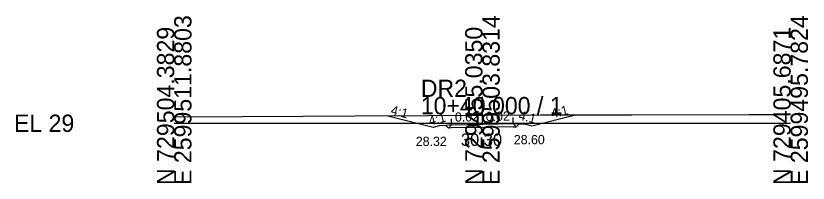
# Model space of a CAD drawing. Extents: x -26 to 1162, y -10 to 9515.
# Drawn here: x -25.7 to 102.8, y 1990.3 to 2017.4 of the extents above; entities that cross this region are included whole.
import ezdxf

# ---------------------------------------------------------------- set-up
doc = ezdxf.new("R2010")
doc.units = 0
for name, color, linetype in [('Exist Cross Section Cell', 7, 'Continuous'), ('Exist XS Center Line Elevation Label', 7, 'Continuous'), ('Exist XS Ground Line', 7, 'Continuous'), ('Prop XS Ditch Slope Text', 7, 'Continuous'), ('Prop XS Ditch Standard Text', 7, 'Continuous'), ('Prop XS Dump Level', 7, 'Continuous'), ('Prop XS EOT Tick Mark', 7, 'Continuous'), ('Prop XS Finish Grade', 7, 'Continuous'), ('Prop XS Finish Grade Earthwork', 7, 'Continuous'), ('Prop XS Finish Grade Pavement', 7, 'Continuous'), ('Prop XS Pvmt Edge Slope', 7, 'Continuous'), ('Prop XS SE Text', 7, 'Continuous'), ('Prop XS Side Slope Text', 7, 'Continuous'), ('Prop XS Subgrade Earthwork', 7, 'Continuous')]:
    doc.layers.add(name, color=color, linetype=linetype)

msp = doc.modelspace()

# ---------------------------------------------------------------- linework, layer by layer
at = {"layer": 'Exist Cross Section Cell'}
for p, q in [((50, 2000), (50, 2004.25)), ((0, 2000), (50, 2000)), ((50, 2000), (100, 2000))]:
    msp.add_line(p, q, dxfattribs=at)
at = {"layer": 'Exist XS Ground Line'}
msp.add_lwpolyline([(0, 2001.04), (11.01, 2001.09), (20.9, 2001.15), (29.35, 2001.19), (41.27, 2001.24), (50, 2001.3), (59.51, 2001.36), (69.47, 2001.38), (74.19, 2001.38), (93.29, 2001.42), (100, 2001.41)], dxfattribs=at)
at = {"layer": 'Prop XS Dump Level'}
for p, q in [((45, 1999.73), (50, 1999.83)), ((50, 1999.83), (55, 1999.93))]:
    msp.add_line(p, q, dxfattribs=at)
at = {"layer": 'Prop XS EOT Tick Mark'}
for p, q in [((45, 1999.73), (45, 2000.73)), ((55, 1999.93), (55, 2000.93))]:
    msp.add_line(p, q, dxfattribs=at)
at = {"layer": 'Prop XS Finish Grade'}
for p, q in [((45, 1999.73), (44.05, 1999.65)), ((55, 1999.93), (55.95, 1999.89))]:
    msp.add_line(p, q, dxfattribs=at)
at = {"layer": 'Prop XS Finish Grade Earthwork'}
for p, q in [((58, 1999.6), (65.1, 2001.37)), ((42, 1999.32), (34.42, 2001.21)), ((43, 1999.57), (42, 1999.32)), ((44.05, 1999.65), (43, 1999.57)), ((55.95, 1999.89), (57, 1999.85)), ((57, 1999.85), (58, 1999.6))]:
    msp.add_line(p, q, dxfattribs=at)
at = {"layer": 'Prop XS Finish Grade Pavement'}
for p, q in [((45, 1999.73), (50, 1999.83)), ((50, 1999.83), (55, 1999.93))]:
    msp.add_line(p, q, dxfattribs=at)
at = {"layer": 'Prop XS Pvmt Edge Slope'}
for p, q in [((44.49, 1999.22), (44.05, 1999.65)), ((45, 1999.73), (44.49, 1999.22)), ((55, 1999.93), (55.49, 1999.44)), ((55.49, 1999.44), (55.95, 1999.89))]:
    msp.add_line(p, q, dxfattribs=at)
at = {"layer": 'Prop XS Subgrade Earthwork'}
for p, q in [((44.49, 1999.22), (44.05, 1999.65)), ((45, 1999.23), (44.49, 1999.22)), ((50, 1999.33), (45, 1999.23)), ((55, 1999.43), (50, 1999.33)), ((55, 1999.43), (55.49, 1999.44)), ((55.49, 1999.44), (55.95, 1999.89))]:
    msp.add_line(p, q, dxfattribs=at)

# ---------------------------------------------------------------- texts
at = {"layer": 'Exist Cross Section Cell'}
for s, p in [('E 2599511.8803', (2.8, 1990)), ('E 2599503.8314', (52.8, 1990)), ('E 2599495.7824', (102.8, 1990)), ('N 729504.3829', (0, 1990)), ('N 729455.0350', (50, 1990)), ('N 729405.6871', (100, 1990))]:
    msp.add_text(s, height=2.8, rotation=90, dxfattribs=at).set_placement(p)
for s, p in [('DR2', (40, 2004.25)), ('10+40.000 / 1', (40, 2001.45)), ('EL 29', (-26, 1998.6))]:
    msp.add_text(s, height=2.8, dxfattribs=at).set_placement(p)
at = {"layer": 'Exist XS Center Line Elevation Label'}
msp.add_text('30.30', height=2, dxfattribs=at).set_placement((46.5, 1996.33))
at = {"layer": 'Prop XS Ditch Slope Text'}
for rotation, p in [(14.0362, (41.48, 1999.62)), (345.9638, (55.78, 2000.62))]:
    msp.add_text('4:1', height=1.5, rotation=rotation, dxfattribs=at).set_placement(p)
at = {"layer": 'Prop XS Ditch Standard Text'}
for s, p in [('28.32', (39.19, 1996.32)), ('28.60', (55.09, 1996.6))]:
    msp.add_text(s, height=1.5, dxfattribs=at).set_placement(p)
at = {"layer": 'Prop XS Dump Level'}
for p in [(43, 1999.53), (57, 1999.81)]:
    msp.add_text('Case1', height=0.04, dxfattribs=at).set_placement(p)
at = {"layer": 'Prop XS SE Text'}
for p in [(45.55, 2000.24), (50.55, 2000.34)]:
    msp.add_text('0.02', height=1.5, rotation=1.1458, dxfattribs=at).set_placement(p)
at = {"layer": 'Prop XS Side Slope Text'}
for rotation, p in [(345.9638, (35.03, 2001.46)), (14.0362, (61.33, 2000.8))]:
    msp.add_text('4:1', height=1.5, rotation=rotation, dxfattribs=at).set_placement(p)

doc.saveas('drawing.dxf')
